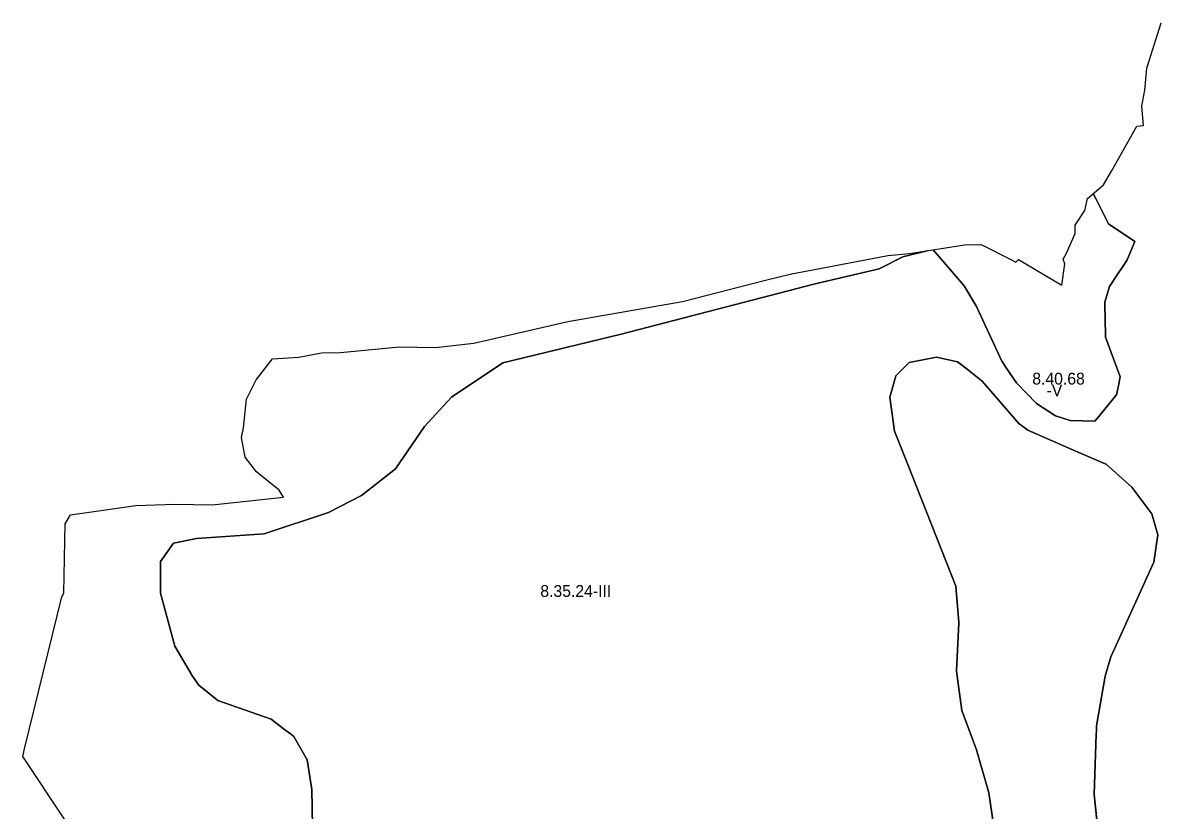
# Model space of a CAD drawing. Extents: x -547623 to -533936, y -1096714 to -1086523.
# Drawn here: x -545672 to -544707, y -1093114 to -1092445 of the extents above; entities that cross this region are included whole.
import ezdxf

# ---------------------------------------------------------------- set-up
doc = ezdxf.new("R2010")
doc.units = 0
doc.layers.add('Vrstva 27', color=7, linetype='Continuous')
doc.layers.add('Vrstva 28', color=7, linetype='Continuous')

msp = doc.modelspace()

# ---------------------------------------------------------------- linework, layer by layer
at = {"layer": 'Vrstva 28'}
for p, q in [((-544761.5, -1092595), (-544763.8, -1092590.25)), ((-544763.8, -1092590.25), (-544761.5, -1092595)), ((-544751, -1092616), (-544761.5, -1092595)), ((-544761.5, -1092595), (-544751, -1092616)), ((-544728.5, -1092631), (-544751, -1092616)), ((-544751, -1092616), (-544728.5, -1092631)), ((-544735, -1092646.5), (-544728.5, -1092631)), ((-544728.5, -1092631), (-544735, -1092646.5)), ((-544945.5, -1092654), (-544925.5, -1092644)), ((-544925.5, -1092644), (-544945.5, -1092654)), ((-544925.5, -1092644), (-544904.8, -1092638.72)), ((-544904.8, -1092638.72), (-544925.5, -1092644)), ((-544899.66, -1092637.9), (-544873.5, -1092668.5)), ((-544873.5, -1092668.5), (-544899.66, -1092637.9)), ((-544738.75, -1092652.12), (-544735, -1092646.5)), ((-544735, -1092646.5), (-544738.75, -1092652.12)), ((-545000, -1092666.77), (-544945.5, -1092654)), ((-544945.5, -1092654), (-545000, -1092666.77)), ((-544742.98, -1092658.47), (-544738.75, -1092652.12)), ((-544738.75, -1092652.12), (-544742.98, -1092658.47)), ((-544750, -1092669), (-544742.98, -1092658.47)), ((-544742.98, -1092658.47), (-544750, -1092669)), ((-545164.5, -1092709.5), (-545001, -1092667)), ((-545001, -1092667), (-545164.5, -1092709.5)), ((-545001, -1092667), (-545000, -1092666.77)), ((-545000, -1092666.77), (-545001, -1092667)), ((-544873.5, -1092668.5), (-544863, -1092686)), ((-544863, -1092686), (-544873.5, -1092668.5)), ((-544754, -1092682.5), (-544750, -1092669)), ((-544750, -1092669), (-544754, -1092682.5)), ((-544753.99, -1092682.9), (-544754, -1092682.5)), ((-544754, -1092682.5), (-544753.99, -1092682.9)), ((-544753.94, -1092685.98), (-544753.99, -1092682.9)), ((-544753.99, -1092682.9), (-544753.94, -1092685.98)), ((-544863, -1092686), (-544843.24, -1092728.74)), ((-544843.24, -1092728.74), (-544863, -1092686)), ((-544753.78, -1092695.52), (-544753.94, -1092685.98)), ((-544753.94, -1092685.98), (-544753.78, -1092695.52)), ((-544753.5, -1092712), (-544753.78, -1092695.52)), ((-544753.78, -1092695.52), (-544753.5, -1092712)), ((-545265, -1092734), (-545164.5, -1092709.5)), ((-545164.5, -1092709.5), (-545265, -1092734)), ((-544743.77, -1092738.07), (-544753.5, -1092712)), ((-544753.5, -1092712), (-544743.77, -1092738.07)), ((-544931.5, -1092745), (-544920, -1092733.5)), ((-544920, -1092733.5), (-544931.5, -1092745)), ((-544920, -1092733.5), (-544897, -1092729)), ((-544897, -1092729), (-544920, -1092733.5)), ((-544897, -1092729), (-544879, -1092733)), ((-544879, -1092733), (-544897, -1092729)), ((-544879, -1092733), (-544870.87, -1092739.39)), ((-544870.87, -1092739.39), (-544879, -1092733)), ((-544843.24, -1092728.74), (-544841.5, -1092732.5)), ((-544841.5, -1092732.5), (-544843.24, -1092728.74)), ((-544841.5, -1092732.5), (-544840.73, -1092733.64)), ((-544840.73, -1092733.64), (-544841.5, -1092732.5)), ((-544840.73, -1092733.64), (-544837.65, -1092738.2)), ((-544837.65, -1092738.2), (-544840.73, -1092733.64)), ((-545308.5, -1092763), (-545265, -1092734)), ((-545265, -1092734), (-545308.5, -1092763)), ((-544870.87, -1092739.39), (-544858, -1092749.5)), ((-544858, -1092749.5), (-544870.87, -1092739.39)), ((-544837.65, -1092738.2), (-544829, -1092751)), ((-544829, -1092751), (-544837.65, -1092738.2)), ((-544742.93, -1092740.32), (-544743.77, -1092738.07)), ((-544743.77, -1092738.07), (-544742.93, -1092740.32)), ((-544741, -1092745.5), (-544742.93, -1092740.32)), ((-544742.93, -1092740.32), (-544741, -1092745.5)), ((-544936.5, -1092763), (-544931.77, -1092745.98)), ((-544931.77, -1092745.98), (-544936.5, -1092763)), ((-544931.77, -1092745.98), (-544931.5, -1092745)), ((-544931.5, -1092745), (-544931.77, -1092745.98)), ((-544858, -1092749.5), (-544827, -1092785.5)), ((-544827, -1092785.5), (-544858, -1092749.5)), ((-544829, -1092751), (-544812, -1092768.5)), ((-544812, -1092768.5), (-544829, -1092751)), ((-544744, -1092761), (-544742.25, -1092751.97)), ((-544742.25, -1092751.97), (-544744, -1092761)), ((-544742.25, -1092751.97), (-544741, -1092745.5)), ((-544741, -1092745.5), (-544742.25, -1092751.97)), ((-544759.09, -1092779.35), (-544744.35, -1092761.43)), ((-544744.35, -1092761.43), (-544759.09, -1092779.35)), ((-544744.35, -1092761.43), (-544744, -1092761)), ((-544744, -1092761), (-544744.35, -1092761.43)), ((-545331.5, -1092788), (-545308.5, -1092763)), ((-545308.5, -1092763), (-545331.5, -1092788)), ((-544932.5, -1092792), (-544936.5, -1092763)), ((-544936.5, -1092763), (-544932.5, -1092792)), ((-544812, -1092768.5), (-544796, -1092779)), ((-544796, -1092779), (-544812, -1092768.5)), ((-544796, -1092779), (-544783.5, -1092783)), ((-544783.5, -1092783), (-544796, -1092779)), ((-544762.5, -1092783.5), (-544759.09, -1092779.35)), ((-544759.09, -1092779.35), (-544762.5, -1092783.5)), ((-545356, -1092824), (-545331.5, -1092788)), ((-545331.5, -1092788), (-545356, -1092824)), ((-544827, -1092785.5), (-544819.5, -1092791)), ((-544819.5, -1092791), (-544827, -1092785.5)), ((-544819.5, -1092791), (-544778.1, -1092809.05)), ((-544778.1, -1092809.05), (-544819.5, -1092791)), ((-544783.5, -1092783), (-544762.5, -1092783.5)), ((-544762.5, -1092783.5), (-544783.5, -1092783)), ((-544922.5, -1092817.28), (-544932.5, -1092792)), ((-544932.5, -1092792), (-544922.5, -1092817.28)), ((-544778.1, -1092809.05), (-544753.73, -1092819.68)), ((-544753.73, -1092819.68), (-544778.1, -1092809.05)), ((-544880.5, -1092923.5), (-544922.5, -1092817.28)), ((-544922.5, -1092817.28), (-544880.5, -1092923.5)), ((-544753.73, -1092819.68), (-544753, -1092820)), ((-544753, -1092820), (-544753.73, -1092819.68)), ((-544753, -1092820), (-544731, -1092839.5)), ((-544731, -1092839.5), (-544753, -1092820)), ((-545375.89, -1092839.43), (-545356, -1092824)), ((-545356, -1092824), (-545375.89, -1092839.43)), ((-545385, -1092846.5), (-545375.89, -1092839.43)), ((-545375.89, -1092839.43), (-545385, -1092846.5)), ((-544731, -1092839.5), (-544714, -1092862)), ((-544714, -1092862), (-544731, -1092839.5)), ((-545413, -1092861), (-545385, -1092846.5)), ((-545385, -1092846.5), (-545413, -1092861)), ((-545467.5, -1092879), (-545413, -1092861)), ((-545413, -1092861), (-545467.5, -1092879)), ((-544714, -1092862), (-544709, -1092880)), ((-544709, -1092880), (-544714, -1092862)), ((-545555.5, -1092902.5), (-545544.5, -1092887)), ((-545544.5, -1092887), (-545555.5, -1092902.5)), ((-545544.5, -1092887), (-545525, -1092883)), ((-545525, -1092883), (-545544.5, -1092887)), ((-545525, -1092883), (-545467.5, -1092879)), ((-545467.5, -1092879), (-545525, -1092883)), ((-544709, -1092880), (-544712.5, -1092903)), ((-544712.5, -1092903), (-544709, -1092880)), ((-545555.5, -1092925.34), (-545555.5, -1092902.5)), ((-545555.5, -1092902.5), (-545555.5, -1092925.34)), ((-544712.5, -1092903), (-544744.51, -1092973.59)), ((-544744.51, -1092973.59), (-544712.5, -1092903)), ((-545555.5, -1092929.5), (-545555.5, -1092925.34)), ((-545555.5, -1092925.34), (-545555.5, -1092929.5)), ((-544878.05, -1092954.41), (-544880.5, -1092923.5)), ((-544880.5, -1092923.5), (-544878.05, -1092954.41)), ((-545543.5, -1092974.5), (-545555.5, -1092929.5)), ((-545555.5, -1092929.5), (-545543.5, -1092974.5)), ((-544880, -1092995.5), (-544878, -1092955)), ((-544878, -1092955), (-544880, -1092995.5)), ((-544878, -1092955), (-544878.05, -1092954.41)), ((-544878.05, -1092954.41), (-544878, -1092955)), ((-545528.52, -1093000), (-545543.5, -1092974.5)), ((-545543.5, -1092974.5), (-545528.52, -1093000)), ((-544744.51, -1092973.59), (-544749, -1092983.5)), ((-544749, -1092983.5), (-544744.51, -1092973.59)), ((-544749, -1092983.5), (-544753.75, -1093000)), ((-544753.75, -1093000), (-544749, -1092983.5)), ((-545523, -1093007.5), (-545528.52, -1093000)), ((-545528.52, -1093000), (-545523, -1093007.5)), ((-544879.39, -1093000), (-544880, -1092995.5)), ((-544880, -1092995.5), (-544879.39, -1093000)), ((-544875.5, -1093029), (-544879.39, -1093000)), ((-544879.39, -1093000), (-544875.5, -1093029)), ((-544753.75, -1093000), (-544761, -1093042)), ((-544761, -1093042), (-544753.75, -1093000)), ((-545507, -1093020.5), (-545523, -1093007.5)), ((-545523, -1093007.5), (-545507, -1093020.5)), ((-545461.5, -1093036.5), (-545507, -1093020.5)), ((-545507, -1093020.5), (-545461.5, -1093036.5)), ((-544865.83, -1093054.92), (-544875.5, -1093029)), ((-544875.5, -1093029), (-544865.83, -1093054.92)), ((-545451.39, -1093044.21), (-545461.5, -1093036.5)), ((-545461.5, -1093036.5), (-545451.39, -1093044.21)), ((-544761, -1093042.03), (-544761.15, -1093046.46)), ((-544761.15, -1093046.46), (-544761, -1093042.03)), ((-544761, -1093042), (-544761, -1093042.03)), ((-544761, -1093042.03), (-544761, -1093042)), ((-545444.17, -1093049.72), (-545451.39, -1093044.21)), ((-545451.39, -1093044.21), (-545444.17, -1093049.72)), ((-545442.5, -1093051), (-545444.17, -1093049.72)), ((-545444.17, -1093049.72), (-545442.5, -1093051)), ((-545431, -1093071), (-545442.5, -1093051)), ((-545442.5, -1093051), (-545431, -1093071)), ((-544761.25, -1093049.17), (-544763, -1093100.5)), ((-544763, -1093100.5), (-544761.25, -1093049.17)), ((-544761.15, -1093046.46), (-544761.25, -1093049.17)), ((-544761.25, -1093049.17), (-544761.15, -1093046.46)), ((-544864.42, -1093058.69), (-544865.83, -1093054.92)), ((-544865.83, -1093054.92), (-544864.42, -1093058.69)), ((-544863.33, -1093061.61), (-544864.42, -1093058.69)), ((-544864.42, -1093058.69), (-544863.33, -1093061.61)), ((-544863, -1093062.5), (-544863.33, -1093061.61)), ((-544863.33, -1093061.61), (-544863, -1093062.5)), ((-545427, -1093096), (-545431, -1093071)), ((-545431, -1093071), (-545427, -1093096)), ((-544852.5, -1093099), (-544863, -1093062.5)), ((-544863, -1093062.5), (-544852.5, -1093099)), ((-545426.5, -1093127.5), (-545427, -1093096)), ((-545427, -1093096), (-545426.5, -1093127.5)), ((-544842.5, -1093166.5), (-544852.5, -1093099)), ((-544852.5, -1093099), (-544842.5, -1093166.5)), ((-544763, -1093100.5), (-544757.39, -1093155.19)), ((-544757.39, -1093155.19), (-544763, -1093100.5))]:
    msp.add_line(p, q, dxfattribs=at)
for points in [[(-545599.87, -1093177), (-545672.5, -1093068.01), (-545670.95, -1093061.66), (-545639.45, -1092932.63), (-545637.57, -1092929.37), (-545636.45, -1092870.67), (-545632.09, -1092862.88), (-545576.43, -1092855.09), (-545543.37, -1092853.84), (-545511.77, -1092854.4), (-545451.21, -1092847.92), (-545454.87, -1092842.03), (-545469.31, -1092830.29), (-545473.99, -1092826.48), (-545483.6, -1092813.89), (-545486.88, -1092797.21), (-545485.08, -1092789.13), (-545482.67, -1092764.77), (-545474.46, -1092748.46), (-545460.63, -1092730.62), (-545438.08, -1092729.18), (-545418.92, -1092725.38), (-545402.85, -1092725.06), (-545352.76, -1092720.39), (-545322.16, -1092720.85), (-545289.56, -1092717.3), (-545209.85, -1092698.84), (-545112.63, -1092681.93), (-545043.12, -1092664.04), (-545020.01, -1092658.34), (-545001.85, -1092654.86), (-544938.2, -1092642.8), (-544919.76, -1092641.12), (-544873.2, -1092633.66), (-544859.36, -1092633.57), (-544855.12, -1092635.42), (-544837.7, -1092644.29), (-544832.65, -1092646.86), (-544829.52, -1092648.46), (-544827.29, -1092646.13), (-544790.63, -1092667.95), (-544788.02, -1092649.85), (-544789.37, -1092645.99), (-544786.52, -1092640.91), (-544779.2, -1092624.08), (-544779.26, -1092617.03), (-544770.89, -1092604.57), (-544768.7, -1092594.48), (-544755.13, -1092582.76), (-544748.39, -1092571.15), (-544726.79, -1092532.88), (-544721.31, -1092532.44), (-544722.55, -1092515.94), (-544720.18, -1092502.28), (-544718.27, -1092483.76), (-544706.2, -1092445.18)], [(-545164.5, -1092709.5), (-545001, -1092667), (-545000, -1092666.77), (-544945.5, -1092654), (-544925.5, -1092644), (-544904.8, -1092638.72)], [(-545426.5, -1093127.5), (-545427, -1093096), (-545431, -1093071), (-545442.5, -1093051), (-545444.17, -1093049.72), (-545451.39, -1093044.21), (-545461.5, -1093036.5), (-545507, -1093020.5), (-545523, -1093007.5), (-545528.52, -1093000), (-545543.5, -1092974.5), (-545555.5, -1092929.5), (-545555.5, -1092925.34), (-545555.5, -1092902.5), (-545544.5, -1092887), (-545525, -1092883), (-545467.5, -1092879), (-545413, -1092861), (-545385, -1092846.5), (-545375.89, -1092839.43), (-545356, -1092824), (-545331.5, -1092788), (-545308.5, -1092763), (-545265, -1092734), (-545164.5, -1092709.5)], [(-544757.39, -1093155.19), (-544763, -1093100.5), (-544761.25, -1093049.17), (-544761.15, -1093046.46), (-544761, -1093042.03), (-544761, -1093042), (-544753.75, -1093000), (-544749, -1092983.5), (-544744.51, -1092973.59), (-544712.5, -1092903), (-544709, -1092880), (-544714, -1092862), (-544731, -1092839.5), (-544753, -1092820), (-544753.73, -1092819.68), (-544778.1, -1092809.05), (-544819.5, -1092791), (-544827, -1092785.5), (-544858, -1092749.5), (-544870.87, -1092739.39), (-544879, -1092733), (-544897, -1092729), (-544920, -1092733.5), (-544931.5, -1092745), (-544931.77, -1092745.98), (-544936.5, -1092763), (-544932.5, -1092792), (-544922.5, -1092817.28)], [(-544922.5, -1092817.28), (-544880.5, -1092923.5), (-544878.05, -1092954.41), (-544878, -1092955), (-544880, -1092995.5), (-544879.39, -1093000), (-544875.5, -1093029), (-544865.83, -1093054.92), (-544864.42, -1093058.69), (-544863.33, -1093061.61), (-544863, -1093062.5), (-544852.5, -1093099), (-544842.5, -1093166.5), (-544842.29, -1093174.21), (-544842.18, -1093177.99), (-544840, -1093256.5), (-544834.59, -1093277.82), (-544834.02, -1093280.04), (-544832, -1093288), (-544816, -1093320), (-544784, -1093358), (-544767.47, -1093374.72), (-544719.39, -1093423.35), (-544697, -1093446)]]:
    msp.add_lwpolyline(points, dxfattribs=at)

# ---------------------------------------------------------------- texts
at = {"layer": 'Vrstva 27'}
for s, p in [('8.40.68', (-544815.62, -1092752.33)), ('-V', (-544803.49, -1092762.33)), ('8.35.24-III', (-545233.19, -1092932.59))]:
    msp.add_text(s, height=10, dxfattribs=at).set_placement(p)

doc.saveas('drawing.dxf')
